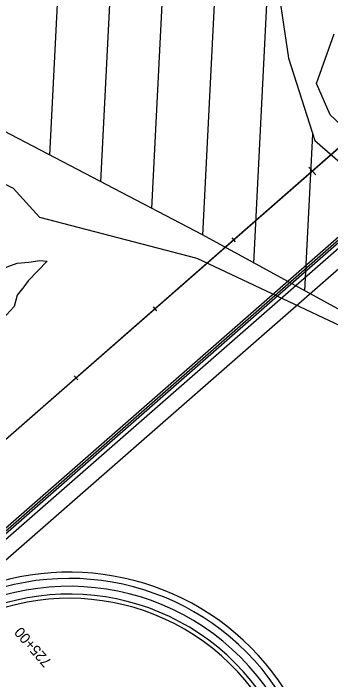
# Model space of a CAD drawing. Extents: x 1300404 to 1323571, y 237813 to 252077.
# Drawn here: x 1311153 to 1311456, y 241084 to 241720 of the extents above; entities that cross this region are included whole.
import ezdxf

# ---------------------------------------------------------------- set-up
doc = ezdxf.new("R2010")
doc.units = 0
for name, color, linetype in [('R_Const Limits', 7, 'Continuous'), ('R_Floodway', 7, 'Continuous'), ('R_Flooplain', 7, 'Continuous'), ('R_Future', 7, 'Continuous'), ('R_Horz Alg Major Ticks', 7, 'Continuous'), ('R_Horz Alg Minor Ticks', 7, 'Continuous'), ('R_Horz Alg Station Annot', 7, 'Continuous'), ('R_Proposed', 7, 'Continuous')]:
    doc.layers.add(name, color=color, linetype=linetype)

msp = doc.modelspace()

# ---------------------------------------------------------------- linework, layer by layer
at = {"layer": 'R_Const Limits'}
for points in [[(1311010.65, 241411.21), (1311011.98, 241412.03), (1311020.7, 241416.94), (1311029.58, 241421.58), (1311038.46, 241426.21), (1311047.23, 241431.03), (1311055.97, 241435.9), (1311064.71, 241440.77), (1311073.58, 241445.42), (1311082.48, 241450.02), (1311091.54, 241454.35), (1311100.71, 241458.51), (1311110.08, 241462.32), (1311119.35, 241466.32), (1311128.65, 241470.24), (1311138.08, 241473.96), (1311147.19, 241478.21), (1311156.69, 241481.81), (1311167.85, 241482.64), (1311178.44, 241484.42), (1311185.37, 241483.83), (1311185.37, 241483.83)], [(1311185.37, 241483.83), (1311167.13, 241464.86), (1311167.15, 241464.85), (1311162.87, 241459.25), (1311156.66, 241451.34), (1311153.67, 241440.35), (1311146.91, 241432.97), (1311139.94, 241425.8), (1311132.94, 241418.66), (1311125.71, 241411.74), (1311119.16, 241404.16), (1311112.06, 241397.12), (1311106.62, 241388.47), (1311100.11, 241380.86), (1311093.57, 241373.27), (1311086.77, 241365.95), (1311080.19, 241358.4), (1311073.62, 241350.85), (1311067.08, 241343.26), (1311060.89, 241335.34), (1311058.51, 241332.25), (1311020.24, 241288.97), (1311020.24, 241288.97)]]:
    msp.add_lwpolyline(points, dxfattribs=at)
at = {"layer": 'R_Floodway'}
for p, q in [((1311187.9, 241584.88), (1311213.4, 242093.9)), ((1311236.69, 241559.43), (1311262.41, 242072.8)), ((1311285.47, 241533.99), (1311311.18, 242047.14)), ((1311334.26, 241508.53), (1311359.66, 242015.5)), ((1311382.99, 241481.95), (1311407.24, 241965.92)), ((1311431.72, 241455.36), (1311439.22, 241604.96))]:
    msp.add_line(p, q, dxfattribs=at)
for points in [[(1313830.5, 242013.29), (1313725.05, 241936.34), (1313624.18, 241854.31), (1313605.13, 241763.33), (1313491.24, 241614.21), (1313390.85, 241541.84), (1313238.35, 241394.67), (1313129.75, 241351.75), (1313002.33, 241319.46), (1312893.25, 241266.88), (1312749.18, 241191.87), (1312719.26, 241174.03), (1312375.34, 241167.16), (1311696.89, 241341.68), (1311497.53, 241419.47), (1311333.82, 241508.77), (1311059.08, 241652.06), (1310740.78, 241795.13), (1310453.25, 241924.55), (1310367.2, 241994.21), (1310267.81, 242111.73), (1309996.24, 242391.57), (1309869.69, 242546.75), (1309624.53, 242919.62)], [(1310379.63, 242680.75), (1310490.18, 242568.72), (1310548.96, 242534.3), (1310676.05, 242414.18), (1310731.56, 242362.99), (1310810.26, 242291.28), (1310887.62, 242241.41), (1310974.87, 242195.88), (1311031.59, 242168.82), (1311109.67, 242133.43), (1311173.76, 242108.43), (1311242.66, 242083.18), (1311339.33, 242032.34), (1311351.04, 242024.49), (1311431.54, 241940.59), (1311405.15, 241750.77), (1311416.02, 241677.63), (1311441.14, 241598.94), (1311547.83, 241506.46), (1311691.44, 241475.03), (1311836.73, 241477.39), (1311974.41, 241472.87)]]:
    msp.add_lwpolyline(points, dxfattribs=at)
at = {"layer": 'R_Flooplain'}
for p, q in [((1311442.64, 241653.31), (1311459.52, 241700.85)), ((1311455.67, 241623.61), (1311442.64, 241653.31)), ((1311488.02, 241592.95), (1311455.67, 241623.61))]:
    msp.add_line(p, q, dxfattribs=at)
msp.add_lwpolyline([(1309009.78, 242685.04), (1309044.07, 242596.21), (1309055.9, 242542.38), (1309352.07, 242367.77), (1309503.16, 242292.41), (1309669.46, 242230.8), (1309815.49, 242150.85), (1309936.66, 242057.64), (1310419.39, 241839.75), (1310733.16, 241727.16), (1311043.67, 241597.79), (1311103.17, 241577.86), (1311152.77, 241553.58), (1311178, 241525.7), (1311328.48, 241486.66), (1311553.07, 241380.98), (1311870.34, 241289.99), (1312137.52, 241213.62)], dxfattribs=at)
at = {"layer": 'R_Future'}
for p, q in [((1311714.76, 241726.24), (1309950.43, 240183.5)), ((1311716.07, 241724.73), (1309951.75, 240181.99)), ((1311717.39, 241723.23), (1309953.06, 240180.49)), ((1311720.02, 241720.22), (1309955.69, 240177.48)), ((1311729.9, 241708.92), (1311093.16, 241152.15))]:
    msp.add_line(p, q, dxfattribs=at)
for radius, start, end in [(245, 246.68093, 113.15991), (239, 234.16397, 118.30111), (231.5, 223.66667, 131.16667), (231.5, 223.66667, 131.16667), (224, 223.66667, 131.16667), (220, 236.50529, 138.89832)]:
    msp.add_arc((1311206.47, 240941.72), radius, start, end, dxfattribs=at)
at = {"layer": 'R_Horz Alg Major Ticks'}
msp.add_lwpolyline([(1311435.47, 241573.68), (1311442.06, 241566.15)], dxfattribs=at)
at = {"layer": 'R_Horz Alg Minor Ticks'}
for points in [[(1311361.84, 241505.98), (1311365.13, 241502.21)], [(1311286.56, 241440.15), (1311289.85, 241436.39)], [(1311211.28, 241374.33), (1311214.57, 241370.56)]]:
    msp.add_lwpolyline(points, dxfattribs=at)
at = {"layer": 'R_Proposed'}
for p, q in [((1308427.57, 238936.91), (1312793.8, 242754.77)), ((1309180.37, 239595.16), (1312398.96, 242409.52))]:
    msp.add_line(p, q, dxfattribs=at)

# ---------------------------------------------------------------- texts
at = {"layer": 'R_Horz Alg Station Annot'}
msp.add_text('725+00', height=10, rotation=131.16667, dxfattribs=at).set_placement((1311190.22, 241101.35))

doc.saveas('drawing.dxf')
